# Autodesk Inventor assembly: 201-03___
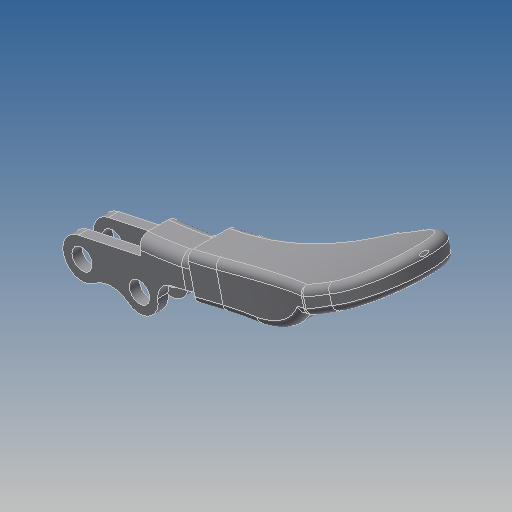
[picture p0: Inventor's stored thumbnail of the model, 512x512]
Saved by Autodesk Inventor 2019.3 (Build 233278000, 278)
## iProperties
Created: 2010-06
Part Number: 201-03___
Material: Ogólny
Document SubType Name: Assembly
Designer: CADENGINEERING4
Author: CADENGINEERING4
Revision Number: ANY
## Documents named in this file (3)
- E:\STRONA\Horizontal toggle clamp\CH-201-AL\201-03___.iam
- E:\STRONA\Horizontal toggle clamp\CH-201-AL\201-A-03___.ipt
- E:\STRONA\Horizontal toggle clamp\CH-201-AL\201-05___.ipt
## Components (2 placed, 2 different names)
1. 201-A-03_??_13
2. 201-05_??_14
